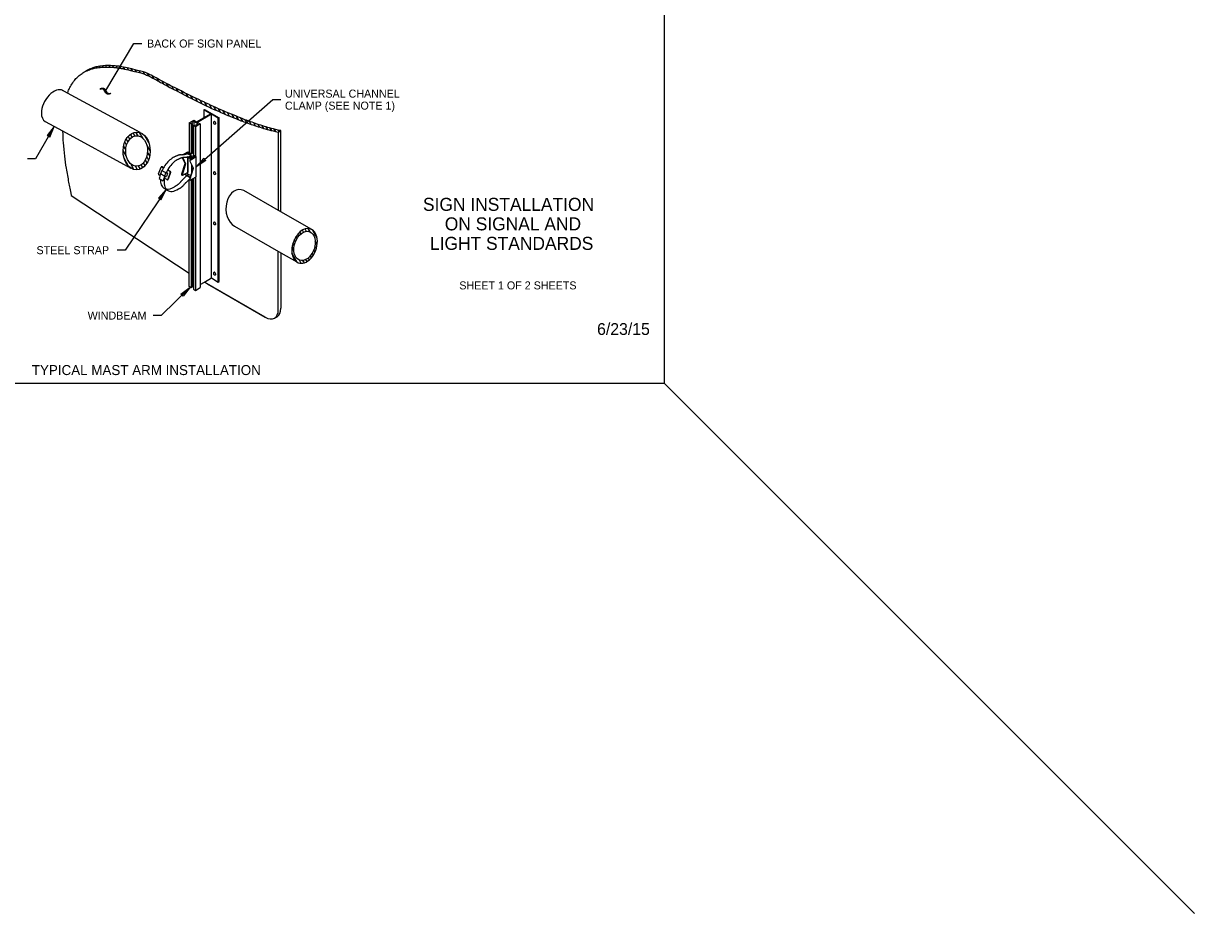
# Model space of a CAD drawing. Extents: x 99862 to 104211, y 98939 to 105076.
# Drawn here: x 101870 to 104211, y 98939 to 100718 of the extents above; entities that cross this region are included whole.
import ezdxf

# ---------------------------------------------------------------- set-up
doc = ezdxf.new("R2010")
doc.units = 0
for name, color, linetype in [('Level 1', 7, 'Continuous'), ('Level 15', 7, 'Continuous'), ('Level 16', 7, 'Continuous'), ('Level 17', 7, 'Continuous'), ('Level 2', 7, 'Continuous'), ('Level 20', 7, 'Continuous'), ('Level 3', 7, 'Continuous'), ('Level 5', 7, 'Continuous'), ('Level 6', 7, 'Continuous'), ('Level 62', 7, 'Continuous'), ('Level 7', 7, 'Continuous'), ('Level 8', 7, 'Continuous')]:
    doc.layers.add(name, color=color, linetype=linetype)

msp = doc.modelspace()

# ---------------------------------------------------------------- linework, layer by layer
at = {"layer": 'Level 1'}
for p, q in [((102010.8, 100628.5), (102010, 100629.9)), ((102016.9, 100629.7), (102015.9, 100631.5)), ((102023.1, 100630.5), (102021.9, 100632.7)), ((102029.6, 100631), (102028.2, 100633.5)), ((102036.3, 100631.1), (102034.7, 100633.9)), ((102043.1, 100631), (102041.4, 100634.1)), ((102050.1, 100630.6), (102048.3, 100633.8)), ((102057.4, 100629.7), (102055.3, 100633.3)), ((102064.7, 100628.7), (102062.7, 100632.3)), ((102072.4, 100627.1), (102070.2, 100630.9)), ((102080.2, 100625.3), (102077.9, 100629.3)), ((101999.4, 100624.9), (101999.1, 100625.4)), ((102005, 100626.9), (102004.4, 100627.8)), ((102088, 100623.5), (102085.5, 100627.8)), ((102095.9, 100621.5), (102093.5, 100625.6)), ((102103.9, 100619.3), (102101.4, 100623.6)), ((102112.3, 100616.5), (102109.6, 100621.2)), ((102121.2, 100612.7), (102118.2, 100618)), ((102130.8, 100607.9), (102127.6, 100613.5)), ((102140.6, 100602.6), (102137.3, 100608.3)), ((102150.4, 100597.3), (102147.1, 100603.1)), ((102160.2, 100592), (102156.8, 100597.8)), ((102169.9, 100586.8), (102166.6, 100592.7)), ((102179.6, 100581.8), (102176.2, 100587.8)), ((102189.3, 100576.7), (102185.7, 100583)), ((102198.9, 100571.8), (102195.1, 100578.4)), ((102208.4, 100567.1), (102204.5, 100573.8)), ((102217.8, 100562.4), (102213.8, 100569.4)), ((102227.2, 100557.8), (102223.1, 100564.9)), ((102236.5, 100553.4), (102232.4, 100560.6)), ((102245.8, 100549.1), (102241.6, 100556.3)), ((102254.9, 100545), (102250.8, 100552.1)), ((102264, 100540.9), (102259.9, 100548)), ((102273, 100537), (102269, 100544)), ((102281.9, 100533.3), (102278, 100540.1)), ((102290.8, 100529.6), (102286.9, 100536.3)), ((102299.6, 100526.1), (102295.8, 100532.7)), ((102308.3, 100522.8), (102304.6, 100529.2)), ((102316.9, 100519.6), (102313.3, 100525.8)), ((102325.4, 100516.5), (102321.9, 100522.6)), ((102333.8, 100513.7), (102330.4, 100519.6)), ((102342.1, 100511), (102338.8, 100516.7)), ((102350.3, 100508.5), (102347.1, 100514)), ((102358.4, 100506.2), (102355.3, 100511.5)), ((102366.3, 100504.1), (102363.4, 100509.2)), ((102374.2, 100502.2), (102371.4, 100507.1)), ((102381, 100502.1), (102379.2, 100505.2)), ((102379.3, 100501.1), (102384.4, 100504.1)), ((102379.3, 100501.1), (102379.3, 100345)), ((102384.4, 100342), (102384.4, 100504.1)), ((101965.4, 100374.7), (102201.1, 100219.2)), ((102379.3, 100146.1), (102379.3, 100262.9)), ((102384.4, 100259.9), (102384.4, 100149.1)), ((102353.4, 100131.2), (102231.6, 100201.5)), ((102231.6, 100201.5), (102237.7, 100198.1)), ((102237.7, 100198.1), (102298, 100163.2)), ((102298, 100163.2), (102353.4, 100131.2)), ((102379.3, 100146.1), (102379.3, 100146.1)), ((102371.7, 100129.3), (102376.9, 100132.3)), ((103150, 100000), (104210.7, 98939.3))]:
    msp.add_line(p, q, dxfattribs=at)
msp.add_lwpolyline([(99862, 99999.5), (103151, 99999.5), (103151, 102075.5), (99862, 102075.5)], close=True, dxfattribs=at)
for centre, start_param, end_param in [((102353.4, 100161), 0.000045, 0.785461), ((102358.6, 100164), 0, 0.785398), ((102353.4, 100161), 5.497787, 6.282485), ((102353.4, 100161), 6.282485, 6.28323)]:
    msp.add_ellipse(centre, major_axis=(18.3, -31.7), ratio=0.57735, start_param=start_param, end_param=end_param, dxfattribs=at)
for points in [[(102088.9, 100626.7), (102085.7, 100628.1), (102077.7, 100629.2), (102062.5, 100632.6), (102054.7, 100633.5), (102039.7, 100634.3), (102032.4, 100634.1), (102018.3, 100632.3), (102011.5, 100630.6), (102001, 100626.5), (101997, 100624.5), (101993.3, 100622.1)], [(101993.3, 100622.1), (101995.4, 100623.2), (101997.7, 100624.2), (102006.3, 100627.6), (102013.1, 100629.3), (102027.2, 100631.1), (102034.5, 100631.3), (102052.7, 100630.7), (102057.3, 100629.6), (102066.7, 100628.6), (102078.7, 100625.5), (102083.7, 100624.5)], [(101958.1, 100579.2), (101958.1, 100579.3), (101958.2, 100579.5), (101961, 100587), (101964.4, 100593.8), (101972.6, 100605.8), (101977.3, 100610.9), (101985.9, 100617.8), (101989.5, 100620.1), (101993.3, 100622.1)], [(102083.7, 100624.5), (102108.7, 100618.9), (102117.8, 100614.4), (102132.3, 100607.5), (102147.6, 100598.4), (102219.4, 100561.1), (102251.7, 100545.8), (102299.9, 100525.8), (102316, 100519.7), (102347.8, 100509), (102363.6, 100504.4), (102379.3, 100501.1)], [(102384.4, 100504.1), (102368.8, 100507.4), (102353, 100511.9), (102321.1, 100522.6), (102305.1, 100528.8), (102256.9, 100548.8), (102224.5, 100564.1), (102159.7, 100595.6), (102129.3, 100613.2), (102120.4, 100616.7), (102115.6, 100620.6), (102088.9, 100626.7)], [(101948.3, 100503.4), (101948.5, 100493), (101949.1, 100482.2), (101951.9, 100451.2), (101954.9, 100430.8), (101960.6, 100398.4), (101962.9, 100386.6), (101965.4, 100374.7)]]:
    msp.add_open_spline(points, degree=3, dxfattribs=at)
at = {"layer": 'Level 15'}
for p, q in [((102034.6, 100584.1), (102090.9, 100678.2)), ((102090.9, 100678.2), (102106.9, 100678.2)), ((102215.1, 100431.9), (102368.6, 100566.1)), ((102368.6, 100566.1), (102384.6, 100566.1)), ((101931.5, 100512.6), (101894.1, 100447.9)), ((101894.1, 100447.9), (101878.1, 100447.9)), ((102155, 100386.4), (102073.2, 100265.2)), ((102073.2, 100265.2), (102057.2, 100265.2)), ((102203, 100191.2), (102145.5, 100134.5)), ((102145.5, 100134.5), (102129.5, 100134.5))]:
    msp.add_line(p, q, dxfattribs=at)
msp.add_lwpolyline([(102034.6, 100584.1), (102035.6, 100582.4), (102036.8, 100580.3), (102037.9, 100579.3), (102039.2, 100578.7), (102040.9, 100578.6), (102044.5, 100579.2), (102043.3, 100577.5), (102043.3, 100577.5), (102043.3, 100577.5), (102041.3, 100576.9), (102039.5, 100576.7), (102037.9, 100577), (102036.4, 100577.8), (102034.6, 100579.4), (102032.6, 100583), (102031.3, 100585.2), (102029.9, 100586.5), (102028.7, 100587.1), (102027.4, 100587.4), (102025.6, 100587.2), (102023.3, 100586.6), (102024.5, 100588.4), (102026.3, 100589), (102028.1, 100589.2), (102029.8, 100588.9), (102031.4, 100588.1), (102033.3, 100586.2), (102034.6, 100584.1)], dxfattribs=at)
for points in [[(101931.5, 100512.6), (101917.5, 100494.3), (101920.6, 100493.7), (101922.7, 100491.3)], [(102215.1, 100431.9), (102230.3, 100449.2), (102231.5, 100446.3), (102234.3, 100444.7)], [(102155, 100386.4), (102139.8, 100369.2), (102142.8, 100368.4), (102144.7, 100365.8)], [(102203, 100191.2), (102188.9, 100173), (102187.5, 100175.9), (102184.7, 100177.3)]]:
    msp.add_lwpolyline(points, close=True, dxfattribs=at)
at = {"layer": 'Level 16'}
for p, q in [((101958.1, 100579.2), (101947.2, 100585.1)), ((101947.2, 100585.1), (101948.8, 100584.3)), ((102103.1, 100500.1), (101958.1, 100579.2)), ((101913.2, 100522.6), (101948.2, 100503.5)), ((101948.2, 100503.5), (102084.4, 100429.2)), ((102384.4, 100342.1), (102310.6, 100384.5)), ((102446.6, 100306.3), (102384.4, 100342.1)), ((102292, 100313.1), (102384.4, 100259.9)), ((102384.5, 100259.9), (102416.2, 100241.7))]:
    msp.add_line(p, q, dxfattribs=at)
for centre, major_axis, ratio, start_param, end_param in [((101931, 100553.4), (17.8, 30.8), 0.57735, 6.283159, 8.63938), ((101931, 100553.4), (17.8, 30.8), 0.57735, 2.356194, 3.141593), ((102301.7, 100348.6), (-0.7, -37.8), 0.717321, 2.830962, 5.943083), ((102431.9, 100273.7), (-12.1, -33.8), 0.665233, 3.009442, 6.116018), ((102431.9, 100273.7), (-12.1, -33.8), 0.665233, 6.11567, 9.292627)]:
    msp.add_ellipse(centre, major_axis=major_axis, ratio=ratio, start_param=start_param, end_param=end_param, dxfattribs=at)
for centre, major_axis, ratio in [((102096.2, 100463.5), (-0.7, -37.8), 0.717321), ((102096.2, 100463.5), (0.5, 30.5), 0.717321), ((102431.9, 100273.7), (10.2, 28.4), 0.665233)]:
    msp.add_ellipse(centre, major_axis=major_axis, ratio=ratio, dxfattribs=at)
at = {"layer": 'Level 17'}
for p, q in [((102198.7, 100458.9), (102195.6, 100457.1)), ((102204.5, 100447), (102196.8, 100451.5)), ((102205.2, 100447.7), (102198.3, 100451.7)), ((102200.6, 100457.8), (102198.7, 100458.9)), ((102203.3, 100452.6), (102206.5, 100450.7)), ((102211.6, 100451.4), (102205.2, 100447.7)), ((102205.2, 100447.4), (102205.2, 100447.7)), ((102207.1, 100458.5), (102205.8, 100457.8)), ((102207.8, 100451.5), (102206.5, 100452.2)), ((102206.5, 100450.7), (102207.8, 100451.5)), ((102207.4, 100460.2), (102208, 100460.5)), ((102208, 100460.5), (102210.1, 100459.3)), ((102210.1, 100455.8), (102209.7, 100455.5)), ((102209.7, 100452.5), (102211.6, 100451.4)), ((102211.6, 100451.1), (102211.6, 100451.4)), ((102192.2, 100417.4), (102198.7, 100421.1)), ((102198.7, 100418.9), (102197.4, 100418.1)), ((102197.4, 100418.1), (102204.3, 100414.2)), ((102192.2, 100417.4), (102192.2, 100416.3)), ((102203.3, 100411), (102192.2, 100417.4)), ((102203.1, 100410.1), (102192.2, 100416.3))]:
    msp.add_line(p, q, dxfattribs=at)
for centre, major_axis, start_param, end_param in [((102203.2, 100459.3), (3.66, 0), 3.926991, 5.497787), ((102205.8, 100459.3), (1.83, 0), 5.497787, 6.816745), ((102212.3, 100454), (3.66, 0), 2.356195, 3.926991), ((102212.3, 100453), (-3.66, 0), 5.802184, 6.033099)]:
    msp.add_ellipse(centre, major_axis=major_axis, ratio=0.57735, start_param=start_param, end_param=end_param, dxfattribs=at)
at = {"layer": 'Level 2'}
for p, q in [((102216.1, 100521.7), (102243.9, 100537.7)), ((102245.5, 100536.8), (102217.7, 100520.7)), ((102230.2, 100545.6), (102231.8, 100546.6)), ((102230.2, 100545.6), (102230.2, 100529.8)), ((102243.9, 100537.7), (102230.2, 100545.6)), ((102231.8, 100546.6), (102260.9, 100529.8)), ((102245.5, 100209.6), (102245.5, 100536.8)), ((102259.3, 100528.8), (102245.5, 100536.8)), ((102201.1, 100519.5), (102210.5, 100524.9)), ((102201.1, 100519.5), (102201.1, 100460.2)), ((102205, 100517.3), (102201.1, 100519.5)), ((102207.4, 100518.7), (102205, 100517.3)), ((102205, 100517.3), (102205, 100457.4)), ((102210.3, 100522.2), (102205.8, 100519.6)), ((102205.8, 100519.6), (102207.4, 100518.7)), ((102207.4, 100518.7), (102207.4, 100458.7)), ((102210.1, 100514.3), (102212.6, 100515.7)), ((102210.1, 100514.3), (102210.1, 100454.9)), ((102214, 100512), (102210.1, 100514.3)), ((102210.3, 100522.2), (102210.3, 100514.4)), ((102218.7, 100517.4), (102210.3, 100522.2)), ((102210.5, 100524.9), (102216.1, 100521.7)), ((102212.6, 100515.7), (102214.2, 100514.8)), ((102223.4, 100517.5), (102214, 100512)), ((102214, 100512), (102214, 100452.7)), ((102214.2, 100514.8), (102218.7, 100517.4)), ((102217.7, 100520.7), (102223.4, 100517.5)), ((102223.4, 100517.5), (102223.4, 100190.3)), ((102260.9, 100529.8), (102259.3, 100528.8)), ((102259.3, 100201.6), (102259.3, 100528.8)), ((102260.9, 100202.6), (102260.9, 100529.8)), ((102201.1, 100219.2), (102201.1, 100406.6)), ((102205, 100405.9), (102205, 100190.1)), ((102207.4, 100407.3), (102207.4, 100191.5)), ((102210.1, 100408.9), (102210.1, 100187.1)), ((102214, 100411.1), (102214, 100184.9)), ((102201.1, 100219.1), (102201.1, 100219.2)), ((102201.1, 100192.3), (102201.1, 100219.1)), ((102231.6, 100201.5), (102245.5, 100209.6)), ((102245.5, 100209.6), (102259.3, 100201.6)), ((102205, 100190.1), (102201.1, 100192.3)), ((102207.4, 100191.5), (102205, 100190.1)), ((102210.1, 100194.9), (102207.4, 100193.3)), ((102210.1, 100187.1), (102214, 100184.9)), ((102214, 100184.9), (102223.4, 100190.3)), ((102223.4, 100196.8), (102231.6, 100201.5)), ((102259.3, 100201.6), (102260.9, 100202.6))]:
    msp.add_line(p, q, dxfattribs=at)
at = {"layer": 'Level 3'}
for p, q in [((102193.1, 100438.6), (102187.8, 100449.8)), ((102187.9, 100455.8), (102198.3, 100461.8)), ((102188.4, 100449.9), (102194, 100438.1)), ((102198.3, 100460.7), (102190.3, 100456.1)), ((102198.3, 100461.8), (102203.5, 100458.8)), ((102198.3, 100460.7), (102198.3, 100458.7)), ((102202.6, 100458.3), (102198.3, 100460.7)), ((102198.3, 100450.6), (102198.3, 100420.9)), ((102203.5, 100458.8), (102202.6, 100458.3)), ((102202.6, 100457.2), (102202.6, 100458.3)), ((102213.3, 100452.1), (102202.6, 100445.9)), ((102202.6, 100445.9), (102203.5, 100445.4)), ((102202.6, 100445.9), (102202.6, 100442.9)), ((102202.6, 100442.9), (102203.5, 100442.4)), ((102202.6, 100442.9), (102209, 100429.5)), ((102203.5, 100457.2), (102203.5, 100458.8)), ((102203.5, 100445.4), (102215.1, 100452.1)), ((102203.5, 100442.4), (102203.5, 100445.4)), ((102209.9, 100428.9), (102203.5, 100442.4)), ((102209, 100454.5), (102209.9, 100455.1)), ((102209, 100453.1), (102209, 100454.5)), ((102209, 100454.5), (102213.3, 100452.1)), ((102215.1, 100452.1), (102209.9, 100455.1)), ((102215.1, 100411.8), (102215.1, 100452.1)), ((102186.7, 100417.7), (102193.1, 100438.6)), ((102187.6, 100417.2), (102186.7, 100417.7)), ((102186.7, 100414.8), (102186.7, 100417.7)), ((102194, 100438.1), (102187.6, 100417.2)), ((102194, 100438.1), (102193.1, 100438.6)), ((102209, 100429.5), (102202.6, 100408.6)), ((102203.5, 100408), (102209.9, 100428.9)), ((102209, 100429.5), (102209.9, 100428.9)), ((102187.6, 100414.2), (102186.7, 100414.8)), ((102187.6, 100417.2), (102187.6, 100414.2)), ((102192.2, 100416.9), (102187.6, 100414.2)), ((102202.6, 100408.6), (102203.5, 100408)), ((102202.6, 100408.6), (102202.6, 100405.6)), ((102202.6, 100405.6), (102203.5, 100405.1)), ((102203.5, 100405.1), (102215.1, 100411.8)), ((102203.5, 100405.1), (102203.5, 100408))]:
    msp.add_line(p, q, dxfattribs=at)
at = {"layer": 'Level 5'}
for p, q in [((102078.9, 100482.1), (102075.6, 100487.8)), ((102082.7, 100487.3), (102079.4, 100492.9)), ((102087.2, 100491.2), (102083.8, 100497)), ((102092.6, 100493.5), (102089, 100499.8)), ((102099.2, 100493.8), (102094.9, 100501.2)), ((102109.1, 100488.3), (102102.1, 100500.5)), ((102120.8, 100479.8), (102112.8, 100493.6)), ((102074.4, 100466.5), (102070.2, 100473.8)), ((102076.1, 100475.3), (102072.5, 100481.5)), ((102123.3, 100463.7), (102116.3, 100475.9)), ((102075.6, 100452.8), (102069.1, 100464.1)), ((102080.7, 100432.1), (102071, 100449)), ((102117, 100439.6), (102113.6, 100445.4)), ((102120.1, 100446), (102116.4, 100452.2)), ((102122.3, 100453.8), (102118, 100461.2)), ((102090.9, 100426.3), (102084.3, 100437.6)), ((102097.9, 100425.8), (102093.7, 100433.1)), ((102103.8, 100427.3), (102100.2, 100433.5)), ((102108.8, 100430.3), (102105.5, 100436)), ((102113.2, 100434.4), (102110, 100440)), ((102424.9, 100297.9), (102422.7, 100301.9)), ((102429.9, 100301.1), (102427.4, 100305.3)), ((102435.6, 100302.8), (102432.8, 100307.6)), ((102443, 100301.7), (102439.1, 100308.5)), ((102456.9, 100289.4), (102447.4, 100305.9)), ((102411.3, 100274.7), (102408.6, 100279.4)), ((102413.7, 100282.3), (102411.3, 100286.5)), ((102416.8, 100288.5), (102414.6, 100292.4)), ((102420.6, 100293.7), (102418.4, 100297.6)), ((102457.1, 100277.3), (102453.2, 100284.1)), ((102417.3, 100241), (102406.6, 100259.4)), ((102410.5, 100264.5), (102406.7, 100271)), ((102445.7, 100250.3), (102443.5, 100254.1)), ((102449.4, 100255.5), (102447.2, 100259.4)), ((102452.7, 100261.5), (102450.3, 100265.7)), ((102455.3, 100268.6), (102452.5, 100273.5)), ((102425.2, 100238.9), (102421.5, 100245.4)), ((102431.4, 100239.9), (102428.6, 100244.7)), ((102436.7, 100242.4), (102434.3, 100246.6)), ((102441.5, 100245.9), (102439.2, 100249.8))]:
    msp.add_line(p, q, dxfattribs=at)
at = {"layer": 'Level 6'}
for centre in [(102252.4, 100519.9), (102252.4, 100419.4), (102252.4, 100319), (102252.4, 100218.5)]:
    msp.add_arc(centre, 2.81, 120, 300, dxfattribs=at)
for centre, major_axis, start_param, end_param in [((102252.4, 100519.9), (-1.41, 2.44), 3.926991, 6.283185), ((102252.4, 100519.9), (1.41, -2.44), 0, 0.785398), ((102252.4, 100419.4), (-1.41, 2.44), 3.926991, 6.283185), ((102252.4, 100419.4), (1.41, -2.44), 0, 0.785398), ((102252.4, 100319), (-1.41, 2.44), 3.926991, 6.283185), ((102252.4, 100319), (1.41, -2.44), 0, 0.785398), ((102252.4, 100218.5), (-1.41, 2.44), 3.926991, 6.283185), ((102252.4, 100218.5), (1.41, -2.44), 0, 0.785398)]:
    msp.add_ellipse(centre, major_axis=major_axis, ratio=0.57735, start_param=start_param, end_param=end_param, dxfattribs=at)
at = {"layer": 'Level 7'}
for p, q in [((102206.1, 100453.1), (102198.3, 100457.6)), ((102198.7, 100437), (102198.7, 100450.4)), ((102206.5, 100452.2), (102206.5, 100450.7)), ((102160.5, 100429.8), (102160.8, 100429.7)), ((102198.7, 100417.4), (102198.7, 100437)), ((102206.5, 100432.5), (102206.5, 100434.9)), ((102206.5, 100421.2), (102206.5, 100432.5)), ((102141.5, 100408.4), (102149.3, 100403.9)), ((102158.9, 100384.2), (102151.1, 100388.7))]:
    msp.add_line(p, q, dxfattribs=at)
for centre, major_axis, start_param, end_param in [((102169.6, 100417.5), (20.1, 34.9), 0.790077, 1.415427), ((102177.3, 100413), (20.1, 34.9), 0.790077, 1.415427), ((102197.4, 100456), (0.92, 1.59), 6.283047, 6.746633), ((102205.2, 100451.5), (0.92, 1.59), 5.497787, 6.746633), ((102176.1, 100415.8), (25.7, 44.4), 1.848795, 2.051453), ((102176.1, 100415.8), (25.7, 44.4), 1.484336, 1.710077), ((102183.9, 100411.3), (25.7, 44.4), 1.484336, 1.708175), ((102179.8, 100415.5), (20.4, 35.3), 1.502117, 1.777139), ((102169.4, 100420.4), (18.3, 31.7), 2.298598, 3.141635), ((102183.9, 100411.3), (25.7, 44.4), 1.848967, 2.051453), ((102177.2, 100415.9), (18.3, 31.7), 2.102369, 4.02394), ((102179.8, 100415.5), (20.4, 35.3), 1.956793, 2.069234), ((102169.4, 100420.4), (18.3, 31.7), 3.355349, 4.02394)]:
    msp.add_ellipse(centre, major_axis=major_axis, ratio=0.57735, start_param=start_param, end_param=end_param, dxfattribs=at)
for points in [[(102197.8, 100457.6), (102188.3, 100455), (102179.5, 100456), (102169.4, 100450.3)], [(102177.2, 100445.8), (102187.3, 100451.6), (102196.1, 100450.6), (102205.6, 100453.1)], [(102196.4, 100414), (102187.4, 100405.8), (102179.1, 100395.5), (102171.9, 100392.1)], [(102179.7, 100387.6), (102186.5, 100390.8), (102194.2, 100400.1), (102202.6, 100408)]]:
    msp.add_open_spline(points, degree=2, dxfattribs=at)
at = {"layer": 'Level 8'}
for p, q in [((102140.2, 100417.6), (102144.9, 100431)), ((102146.5, 100424.7), (102144.1, 100418)), ((102144.1, 100418), (102145, 100417.5)), ((102145, 100417.5), (102145.8, 100417)), ((102147.4, 100432.1), (102146.2, 100432.1)), ((102147.6, 100425.2), (102146.5, 100424.7)), ((102146.8, 100431.9), (102150.1, 100430)), ((102148, 100431.9), (102150.4, 100430.5)), ((102152.4, 100413.2), (102154.7, 100419.9)), ((102154.7, 100419.9), (102158.1, 100419.3)), ((102158.1, 100419.3), (102155.8, 100412.7)), ((102158.1, 100419.3), (102156, 100420.6)), ((102158.3, 100425.3), (102162.3, 100423)), ((102163, 100420.5), (102158.3, 100407.2)), ((102158.6, 100425.8), (102163.5, 100422.9)), ((102164.2, 100420.5), (102159.5, 100407.2)), ((102143.1, 100414), (102140.9, 100415.2)), ((102145.8, 100417), (102146.9, 100416.4)), ((102146.9, 100416.4), (102147.6, 100415.9)), ((102147.6, 100415.9), (102148.7, 100415.4)), ((102148.7, 100415.4), (102149.4, 100414.9)), ((102149.4, 100414.9), (102150.5, 100414.3)), ((102150.5, 100414.3), (102151.3, 100413.8)), ((102151.3, 100413.8), (102152.4, 100413.2)), ((102156.4, 100406.3), (102152.1, 100408.8)), ((102152.4, 100413.2), (102155.8, 100412.7)), ((102157, 100406.1), (102158.1, 100406.1))]:
    msp.add_line(p, q, dxfattribs=at)
msp.add_lwpolyline([(102146.5, 100424.7), (102147.4, 100424.2), (102148.1, 100423.7), (102149.2, 100423.1), (102150, 100422.6), (102151.1, 100422), (102151.8, 100421.6), (102152.9, 100421), (102153.6, 100420.5), (102154.7, 100419.9)], dxfattribs=at)
for centre, start_param, end_param in [((102141.5, 100416.9), 4.302915, 5.873712), ((102146.2, 100430.3), 2.732119, 4.302916), ((102147.4, 100430.2), 2.732119, 3.141593), ((102161.7, 100421.3), 1.161323, 2.732119), ((102162.9, 100421.3), 1.161323, 2.732119), ((102157, 100407.9), 5.873712, 7.444508), ((102158.2, 100407.9), 6.283185, 7.444508)]:
    msp.add_ellipse(centre, major_axis=(-0.03, -1.83), ratio=0.777097, start_param=start_param, end_param=end_param, dxfattribs=at)

# ---------------------------------------------------------------- texts
at = {"layer": 'Level 1'}
msp.add_text('6/23/15', height=23.62, dxfattribs=at).set_placement((103016.5, 100095.8))
at = {"layer": 'Level 20'}
for s, height, p in [('BACK OF SIGN PANEL', 16, (102117, 100670.2)), ('UNIVERSAL CHANNEL', 16, (102392.6, 100570.1)), ('CLAMP (SEE NOTE 1)', 16, (102392.6, 100546.1)), ('STEEL STRAP', 16, (101896.1, 100257.2)), ('WINDBEAM', 16, (101998.3, 100126.5)), ('TYPICAL MAST ARM INSTALLATION', 20, (101886.7, 100015.6))]:
    msp.add_text(s, height=height, dxfattribs=at).set_placement(p)
at = {"layer": 'Level 62'}
for s, height, p in [('SIGN INSTALLATION', 26, (102668.5, 100343.8)), ('ON SIGNAL AND', 26, (102712.1, 100304.8)), ('LIGHT STANDARDS', 26, (102682.5, 100265.8)), ('SHEET 1 OF 2 SHEETS', 16, (102741.1, 100186.8))]:
    msp.add_text(s, height=height, dxfattribs=at).set_placement(p)

doc.saveas('drawing.dxf')
